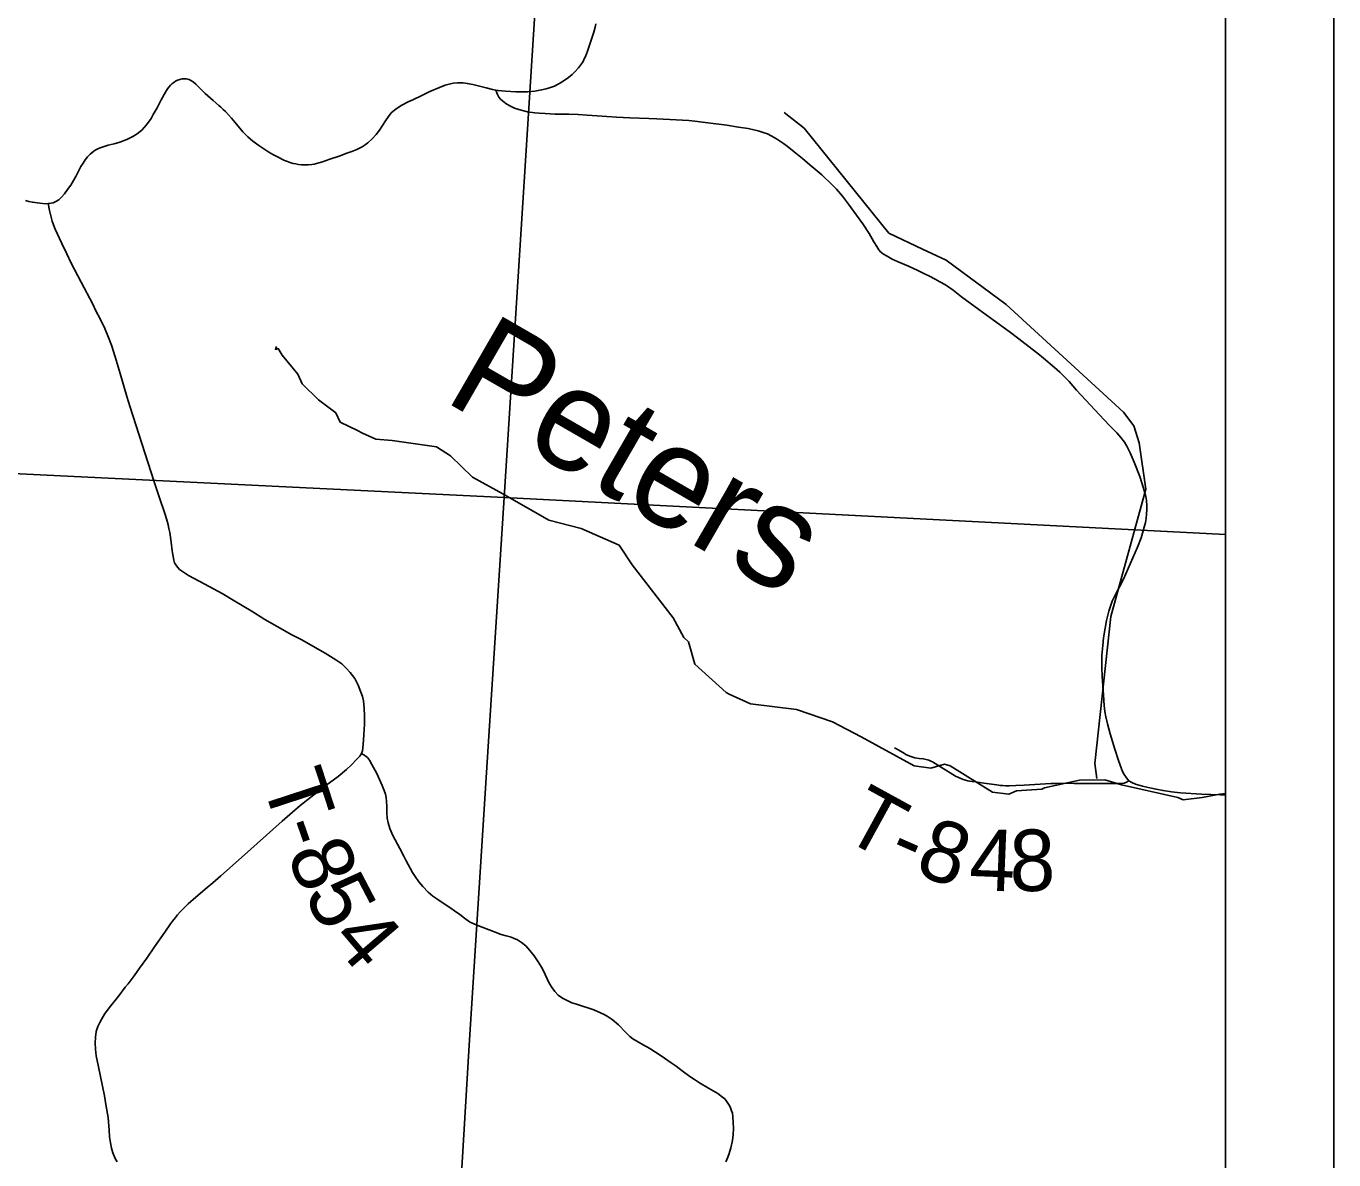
# Model space of a CAD drawing. Extents: x 0 to 34, y 0 to 22.
# Drawn here: x 7.791 to 9, y 16.555 to 17.604 of the extents above; entities that cross this region are included whole.
import ezdxf

# ---------------------------------------------------------------- set-up
doc = ezdxf.new("R2010")
doc.units = 0
for name, color, linetype in [('Default', 7, 'Continuous'), ('GM_X_County_Road', 7, 'Continuous'), ('GM_X_Minor_River', 7, 'Continuous'), ('GM_X_Minor_River_Text', 7, 'Continuous'), ('GM_X_Section', 7, 'Continuous'), ('GM_X_Township_Road', 7, 'Continuous'), ('GM_X_Township_Road_Text', 7, 'Continuous'), ('SH_Cut_Line', 7, 'Continuous'), ('SH_Data', 7, 'Continuous')]:
    doc.layers.add(name, color=color, linetype=linetype)

msp = doc.modelspace()

# ---------------------------------------------------------------- linework, layer by layer
at = {"layer": 'Default'}
msp.add_lwpolyline([(8.9, 14.1), (8.9, 19.1797), (8.8731, 19.181), (8.4872, 19.2008), (7.1944, 19.2649), (6.2536, 19.3066), (6.2282, 18.9116), (6.1917, 18.3385), (6.1723, 18.0255), (6.1151, 17.0743), (6.0901, 16.6706), (6.0633, 16.2368)], dxfattribs=at)
msp.add_lwpolyline([(8.9, 17.1336), (8.9, 18.1799), (8.299, 18.2095), (8.2333, 17.168)], close=True, dxfattribs=at)
at = {"layer": 'GM_X_County_Road'}
for points in [[(7.8119, 17.4397), (7.8127, 17.4397), (7.8164, 17.4405), (7.8189, 17.4416), (7.8216, 17.4433), (7.8242, 17.4457), (7.8268, 17.4487), (7.8298, 17.4527), (7.8326, 17.4569), (7.8351, 17.4611), (7.8373, 17.4647), (7.8421, 17.4739), (7.8442, 17.4772), (7.8461, 17.4803), (7.8483, 17.4831), (7.8505, 17.4853), (7.8526, 17.4871), (7.8553, 17.489), (7.8576, 17.4903), (7.8598, 17.4912), (7.8626, 17.4921), (7.8671, 17.4936), (7.8727, 17.4951), (7.8781, 17.4966), (7.8844, 17.4989), (7.8899, 17.5016), (7.894, 17.5042), (7.8983, 17.5075), (7.9028, 17.5125), (7.907, 17.5185), (7.9089, 17.522), (7.9124, 17.5282), (7.9163, 17.5358), (7.9202, 17.5429), (7.9221, 17.5458), (7.9234, 17.5474), (7.9249, 17.5492), (7.9262, 17.5504), (7.9278, 17.5517), (7.9295, 17.5528), (7.9312, 17.5537), (7.9327, 17.5543), (7.9343, 17.5548), (7.9356, 17.555), (7.937, 17.5551), (7.9381, 17.5552), (7.9392, 17.5551), (7.9406, 17.5549), (7.9421, 17.5544), (7.9438, 17.5535), (7.9457, 17.5523), (7.9483, 17.55), (7.9511, 17.5475), (7.9568, 17.5416), (7.9642, 17.535), (7.9695, 17.5305), (7.9715, 17.5288), (7.9736, 17.5268), (7.9756, 17.5249), (7.9785, 17.5217), (7.9813, 17.5186), (7.9858, 17.5132), (7.9917, 17.506), (7.9935, 17.5041), (7.9964, 17.5014), (8.001, 17.4975), (8.0064, 17.4934), (8.0112, 17.4902), (8.0156, 17.4873), (8.0199, 17.4848), (8.0236, 17.4828), (8.0303, 17.4796), (8.0331, 17.4785), (8.036, 17.4775), (8.0381, 17.4769), (8.0408, 17.4764), (8.0433, 17.476), (8.046, 17.4757), (8.049, 17.4755), (8.0521, 17.4754), (8.0555, 17.4758), (8.0576, 17.4761), (8.0599, 17.4767), (8.0653, 17.4784), (8.0721, 17.4807), (8.0808, 17.4837), (8.0877, 17.4862), (8.0923, 17.4879), (8.097, 17.4898), (8.0994, 17.4909), (8.1021, 17.4923), (8.1047, 17.494), (8.1073, 17.496), (8.1113, 17.4995), (8.1149, 17.5035), (8.1179, 17.5075), (8.1237, 17.5161), (8.1263, 17.5202), (8.1289, 17.5235), (8.1319, 17.5261), (8.1344, 17.528), (8.1386, 17.5306), (8.1446, 17.5337), (8.1488, 17.5357), (8.1571, 17.5397), (8.1644, 17.5433), (8.1736, 17.5472), (8.1786, 17.5491), (8.1823, 17.5501), (8.1861, 17.551), (8.1902, 17.5515), (8.1954, 17.5513), (8.1991, 17.5508), (8.2042, 17.5499), (8.2104, 17.5484), (8.2165, 17.5468), (8.2224, 17.5453), (8.2254, 17.5447), (8.2276, 17.5443), (8.2346, 17.5437), (8.2441, 17.5431), (8.2487, 17.543), (8.2548, 17.5432), (8.2615, 17.5438), (8.2678, 17.5449), (8.2721, 17.5459), (8.2762, 17.547), (8.2797, 17.5483), (8.2826, 17.5498), (8.2858, 17.5516), (8.2928, 17.5564), (8.296, 17.5591), (8.2986, 17.5614), (8.302, 17.5653), (8.3046, 17.5688), (8.3061, 17.5711), (8.3073, 17.5735), (8.3084, 17.5758), (8.3103, 17.5806), (8.3134, 17.5898), (8.3161, 17.5982), (8.3173, 17.6027), (8.3178, 17.606)], [(7.7907, 17.4426), (7.7938, 17.4417), (7.7973, 17.441), (7.804, 17.4401), (7.8094, 17.4396), (7.8119, 17.4397)]]:
    msp.add_lwpolyline(points, dxfattribs=at)
at = {"layer": 'GM_X_Minor_River'}
for points in [[(8.781, 16.9081), (8.7791, 16.9219), (8.7939, 17.0579), (8.8263, 17.1755), (8.8201, 17.2185), (8.8153, 17.2342), (8.8055, 17.2468), (8.6973, 17.3463), (8.6418, 17.3873), (8.6198, 17.3977), (8.5888, 17.4124), (8.5105, 17.5094), (8.492, 17.524)], [(8.9, 16.8941), (8.8946, 16.8937), (8.8784, 16.8906), (8.8606, 16.8883), (8.8557, 16.8906), (8.8039, 16.9023), (8.7884, 16.9068), (8.765, 16.9067), (8.7325, 16.8994), (8.7302, 16.8983), (8.7068, 16.8967), (8.6996, 16.8937), (8.6845, 16.8955), (8.6455, 16.9198), (8.6402, 16.9213), (8.6274, 16.9178), (8.6122, 16.9197), (8.5631, 16.9466), (8.5366, 16.9606), (8.5033, 16.9719), (8.461, 16.9771), (8.4413, 16.9862), (8.4383, 16.9877), (8.4095, 17.0138), (8.4035, 17.0344), (8.3993, 17.0385), (8.3895, 17.0568), (8.3516, 17.1057), (8.3395, 17.1239), (8.3043, 17.1394), (8.2745, 17.1469), (8.2321, 17.1712), (8.2041, 17.1867), (8.1837, 17.2064), (8.1708, 17.2147), (8.1296, 17.2207), (8.1145, 17.2218), (8.1024, 17.2275), (8.0978, 17.2298), (8.0816, 17.2377), (8.0778, 17.2461), (8.0615, 17.2582), (8.0464, 17.273), (8.0426, 17.2821), (8.0282, 17.2995), (8.0244, 17.3056), (8.0218, 17.3048), (8.0229, 17.3075)]]:
    msp.add_lwpolyline(points, dxfattribs=at)
at = {"layer": 'GM_X_Section'}
for points in [[(8.299, 18.2095), (8.2333, 17.168), (7.1862, 17.219), (7.2546, 18.2574)], [(8.2333, 17.168), (8.2168, 16.9137), (8.2009, 16.6614), (8.1857, 16.4083), (8.1692, 16.1543), (8.0945, 16.1581), (8.0152, 16.1622), (7.938, 16.1663), (7.8569, 16.1703), (7.7763, 16.1745), (7.6973, 16.1784), (7.6162, 16.1827), (7.5294, 16.1877), (7.4574, 16.1913), (7.3717, 16.1957), (7.289, 16.1999), (7.2077, 16.2041), (7.123, 16.2082), (7.1862, 17.219)]]:
    msp.add_lwpolyline(points, close=True, dxfattribs=at)
at = {"layer": 'GM_X_Township_Road'}
for points in [[(8.9, 16.8927), (8.8948, 16.8929), (8.8778, 16.8936), (8.8582, 16.8948), (8.85, 16.8957), (8.8422, 16.8969), (8.8357, 16.8981), (8.8285, 16.8998), (8.8231, 16.9011), (8.8168, 16.903), (8.8134, 16.9043), (8.8106, 16.9059), (8.8083, 16.9086), (8.8063, 16.9117), (8.8048, 16.9145), (8.8037, 16.9169), (8.801, 16.9247), (8.7976, 16.9353), (8.7933, 16.9494), (8.7908, 16.9585), (8.7893, 16.9652), (8.7884, 16.97), (8.7878, 16.9757), (8.787, 16.9853), (8.7859, 17.0027), (8.7855, 17.0108), (8.7857, 17.0219), (8.7864, 17.0311), (8.7871, 17.0383), (8.7887, 17.0471), (8.7899, 17.0542), (8.7911, 17.0591), (8.7921, 17.0629), (8.7938, 17.0683), (8.7952, 17.072), (8.7982, 17.0782), (8.8057, 17.0924), (8.8186, 17.122), (8.8218, 17.1306), (8.8259, 17.1447), (8.8266, 17.1486), (8.827, 17.1529), (8.8272, 17.1567), (8.8273, 17.1601), (8.8268, 17.1651), (8.8261, 17.1688), (8.8242, 17.1766), (8.8207, 17.1873), (8.8155, 17.2006), (8.8117, 17.2092), (8.8088, 17.2154), (8.8064, 17.2191), (8.803, 17.2234), (8.7995, 17.2276), (8.7927, 17.2346), (8.7876, 17.2399), (8.7622, 17.2673), (8.7555, 17.2752), (8.7509, 17.2799), (8.7467, 17.2838), (8.7419, 17.2882), (8.7318, 17.2967), (8.7265, 17.301), (8.7212, 17.3052), (8.7089, 17.3148), (8.6999, 17.3214), (8.6855, 17.332), (8.672, 17.3418), (8.6559, 17.3536), (8.6481, 17.3596), (8.6411, 17.3645), (8.6359, 17.3674), (8.6315, 17.3697), (8.6262, 17.3726), (8.6212, 17.3752), (8.6154, 17.3779), (8.6068, 17.3819), (8.5975, 17.3858), (8.5918, 17.3884), (8.5871, 17.391), (8.5837, 17.3929), (8.5811, 17.3951), (8.5795, 17.3971), (8.5775, 17.3999), (8.5749, 17.4045), (8.5705, 17.412), (8.5648, 17.4211), (8.5589, 17.429), (8.5513, 17.4393), (8.5459, 17.4465), (8.5405, 17.4531), (8.5363, 17.4571), (8.5268, 17.4663), (8.5156, 17.4755), (8.5088, 17.4813), (8.5013, 17.4875), (8.4949, 17.4927), (8.4915, 17.4953), (8.485, 17.4996), (8.4801, 17.5024), (8.4765, 17.5041), (8.4727, 17.5056), (8.4681, 17.5069), (8.4639, 17.5079), (8.4586, 17.5091), (8.4498, 17.5105), (8.4391, 17.5121), (8.4214, 17.5145), (8.4164, 17.5151), (8.4095, 17.5158), (8.404, 17.5164), (8.3922, 17.5171), (8.3743, 17.5181), (8.3668, 17.5184), (8.3495, 17.519), (8.3371, 17.5196), (8.3191, 17.5209), (8.3099, 17.5216), (8.3017, 17.5222), (8.293, 17.5225), (8.2804, 17.5225), (8.271, 17.523), (8.2656, 17.5232), (8.2615, 17.5236), (8.2548, 17.5246), (8.2488, 17.526), (8.2429, 17.528), (8.2385, 17.5301), (8.2349, 17.5324), (8.2317, 17.5346), (8.2298, 17.5363), (8.2284, 17.5381), (8.227, 17.5407), (8.2254, 17.5447)], [(7.9249, 16.7737), (7.9267, 16.7762), (7.9294, 16.7796), (7.9314, 16.782), (7.9339, 16.7847), (7.9382, 16.7892), (7.9413, 16.7922), (7.9484, 16.7983), (7.9588, 16.8072), (7.964, 16.8116), (7.9715, 16.8181), (7.9906, 16.8349), (8.0282, 16.8685), (8.0448, 16.8832), (8.0545, 16.8907), (8.0685, 16.9015), (8.0799, 16.91), (8.0875, 16.9164), (8.092, 16.9207), (8.0969, 16.9256), (8.0998, 16.9289), (8.1015, 16.9311), (8.1022, 16.9337), (8.1028, 16.9394), (8.1035, 16.9486), (8.104, 16.9582), (8.1043, 16.9661), (8.1039, 16.9732), (8.1031, 16.9798), (8.1022, 16.9839), (8.1009, 16.9879), (8.0983, 16.9944), (8.0951, 17.0005), (8.091, 17.0061), (8.0873, 17.0102), (8.0832, 17.014), (8.0777, 17.0179), (8.0677, 17.0241), (8.0455, 17.0365), (8.037, 17.0411), (8.0235, 17.0486), (8.0119, 17.0552), (7.9993, 17.0631), (7.9844, 17.0722), (7.9727, 17.0791), (7.9645, 17.0835), (7.952, 17.0903), (7.9416, 17.0959), (7.9361, 17.0996), (7.9333, 17.1015), (7.9303, 17.1049), (7.9286, 17.1075), (7.9279, 17.11), (7.9272, 17.1134), (7.9264, 17.1187), (7.9254, 17.1266), (7.9241, 17.1355), (7.9234, 17.1394), (7.9227, 17.1428), (7.9217, 17.146), (7.9201, 17.1514), (7.9184, 17.1568), (7.916, 17.164), (7.9094, 17.1834), (7.8876, 17.2515), (7.8844, 17.2613), (7.8782, 17.2827), (7.8738, 17.2979), (7.8703, 17.3088), (7.8676, 17.316), (7.8641, 17.3241), (7.8598, 17.333), (7.856, 17.3406), (7.853, 17.3467), (7.8424, 17.3671), (7.8332, 17.3845), (7.8289, 17.3933), (7.8243, 17.4027), (7.8182, 17.4161), (7.8166, 17.42), (7.8154, 17.4236), (7.8142, 17.4283), (7.8128, 17.4346), (7.8121, 17.4387), (7.8119, 17.4397)], [(8.594, 16.9365), (8.5959, 16.9355), (8.5981, 16.9343), (8.6017, 16.932), (8.6052, 16.93), (8.6092, 16.9283), (8.6128, 16.9273), (8.6169, 16.9266), (8.6206, 16.9263), (8.6232, 16.9258), (8.6258, 16.9251), (8.6276, 16.9242), (8.6292, 16.9235), (8.6365, 16.9189), (8.6502, 16.9104), (8.6548, 16.9083), (8.6573, 16.9072), (8.6595, 16.9065), (8.6616, 16.9059), (8.6634, 16.9057), (8.6657, 16.9054), (8.669, 16.9051), (8.6724, 16.9045), (8.6766, 16.9038), (8.6886, 16.9021), (8.6917, 16.9017), (8.6941, 16.9015), (8.6965, 16.9014), (8.6999, 16.9014), (8.706, 16.9017), (8.7138, 16.9019), (8.7286, 16.9028), (8.7335, 16.9032), (8.7385, 16.9034), (8.744, 16.9035), (8.7521, 16.9037), (8.76, 16.9036), (8.7811, 16.9034), (8.7985, 16.9034), (8.8042, 16.9034), (8.8062, 16.9038), (8.8084, 16.9047), (8.8106, 16.9059)], [(8.4382, 16.5535), (8.44, 16.5579), (8.4412, 16.5612), (8.4428, 16.5666), (8.4441, 16.5733), (8.4449, 16.5788), (8.4451, 16.5844), (8.445, 16.59), (8.4446, 16.5953), (8.4441, 16.5987), (8.4434, 16.6009), (8.442, 16.6044), (8.4407, 16.6069), (8.4388, 16.6097), (8.4371, 16.6118), (8.4351, 16.6134), (8.4306, 16.6168), (8.422, 16.6218), (8.4139, 16.6267), (8.4092, 16.6297), (8.4049, 16.6325), (8.3978, 16.6379), (8.3923, 16.642), (8.3877, 16.6451), (8.3784, 16.6515), (8.3679, 16.6583), (8.3616, 16.6617), (8.3559, 16.6652), (8.3522, 16.6674), (8.3493, 16.6696), (8.3453, 16.6736), (8.3388, 16.6803), (8.3329, 16.6853), (8.3294, 16.6877), (8.3257, 16.6899), (8.3224, 16.6914), (8.3161, 16.6941), (8.3, 16.6993), (8.2958, 16.7008), (8.2907, 16.703), (8.287, 16.7049), (8.2831, 16.7079), (8.2801, 16.711), (8.2775, 16.7145), (8.2749, 16.7187), (8.2711, 16.7269), (8.2685, 16.7322), (8.2654, 16.7376), (8.2611, 16.7441), (8.257, 16.7489), (8.2532, 16.7533), (8.2492, 16.7565), (8.2457, 16.7588), (8.2419, 16.7605), (8.2388, 16.7616), (8.2352, 16.7627), (8.2306, 16.7639), (8.2235, 16.7665), (8.2128, 16.7706), (8.2059, 16.7735), (8.2013, 16.7757), (8.1967, 16.7789), (8.1922, 16.7822), (8.1874, 16.7858), (8.1838, 16.7882), (8.1778, 16.7923), (8.1709, 16.7968), (8.1673, 16.7993), (8.1629, 16.8031), (8.158, 16.8081), (8.1544, 16.8125), (8.1509, 16.8175), (8.1486, 16.8211), (8.1463, 16.8253), (8.1428, 16.832), (8.1405, 16.8364), (8.1367, 16.8435), (8.1303, 16.8555), (8.1276, 16.8618), (8.1259, 16.8671), (8.1252, 16.8713), (8.1248, 16.8763), (8.1247, 16.8825), (8.1245, 16.8868), (8.1242, 16.8906), (8.1235, 16.8937), (8.1223, 16.8971), (8.1206, 16.9015), (8.1154, 16.9126), (8.1108, 16.9211), (8.1088, 16.925), (8.1069, 16.9275), (8.1044, 16.9294), (8.1015, 16.9311)], [(7.8755, 16.5535), (7.8737, 16.5568), (7.8716, 16.5619), (7.8703, 16.5663), (7.8693, 16.5713), (7.8686, 16.5766), (7.8682, 16.5829), (7.8671, 16.5946), (7.8652, 16.6067), (7.8638, 16.6148), (7.8582, 16.6416), (7.8563, 16.6518), (7.8554, 16.6578), (7.8551, 16.6633), (7.8554, 16.6688), (7.8563, 16.6742), (7.8578, 16.6789), (7.8594, 16.6825), (7.8614, 16.686), (7.8639, 16.6901), (7.8683, 16.696), (7.877, 16.7072), (7.8831, 16.715), (7.8857, 16.7183), (7.8912, 16.7256), (7.8962, 16.7326), (7.903, 16.7421), (7.9101, 16.7523), (7.9195, 16.7661), (7.9249, 16.7737)]]:
    msp.add_lwpolyline(points, dxfattribs=at)
at = {"layer": 'SH_Cut_Line'}
msp.add_lwpolyline([(8.9, 14.1), (8.9, 20.9), (2.1, 20.9), (2.1, 14.1)], dxfattribs=at)
at = {"layer": 'SH_Data'}
for p, q in [((9, 21), (9, 14)), ((8.9, 20.9), (8.9, 14.1))]:
    msp.add_line(p, q, dxfattribs=at)

# ---------------------------------------------------------------- texts
at = {"layer": 'GM_X_Minor_River_Text'}
msp.add_text('Peters', height=0.0947, rotation=329.9981, dxfattribs=at).set_placement((8.1756, 17.2583))
at = {"layer": 'GM_X_Township_Road_Text'}
for s, rotation, p in [('T', 288.1334, (8.0091, 16.9054)), ('T', 331.284, (8.5435, 16.8543)), ('-', 289.1162, (8.0226, 16.864)), ('8', 340.4651, (8.6112, 16.8204)), ('4', 357.7233, (8.6624, 16.8052)), ('8', 0.7219, (8.7006, 16.8038)), ('8', 292.8593, (8.0317, 16.8382)), ('-', 336.2262, (8.5856, 16.8315)), ('5', 297.6236, (8.0475, 16.8013)), ('4', 310.4716, (8.0715, 16.7588))]:
    msp.add_text(s, height=0.0568, rotation=rotation, dxfattribs=at).set_placement(p)

doc.saveas('drawing.dxf')
